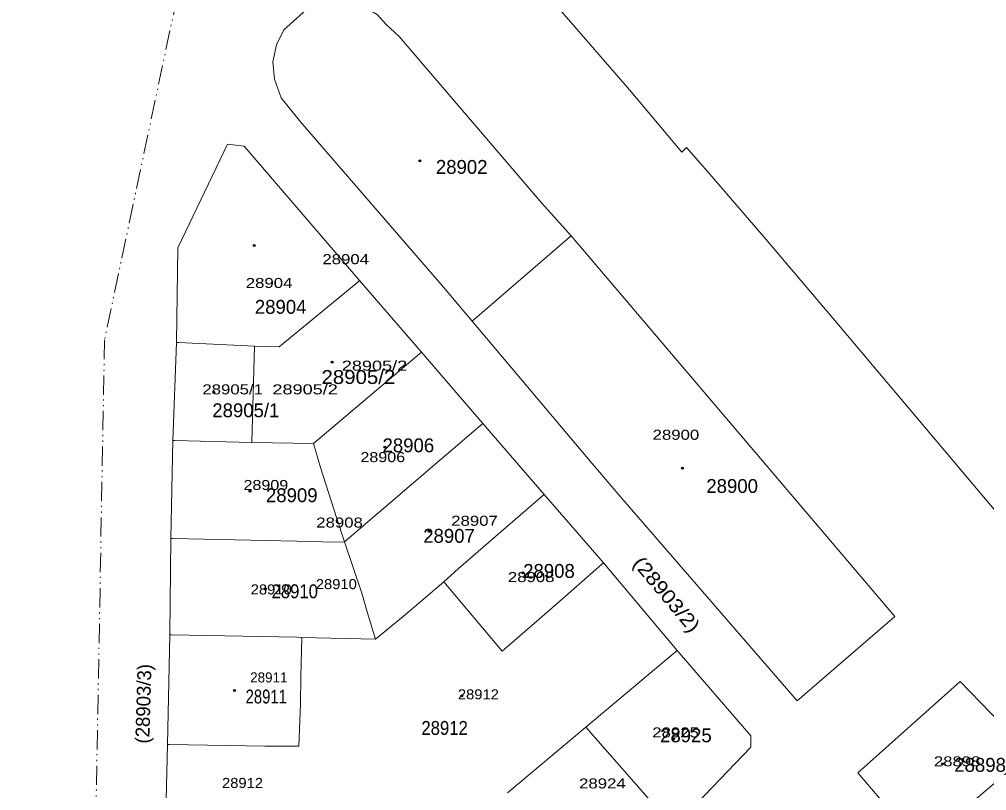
# Model space of a CAD drawing. Extents: x 650553 to 652508, y 239277 to 241647.
# Drawn here: x 650553 to 650803.9, y 240505.5 to 240705.5 of the extents above; entities that cross this region are included whole.
import ezdxf

# ---------------------------------------------------------------- set-up
doc = ezdxf.new("R2010")
doc.units = 0
doc.header["$PDMODE"] = 32
doc.header["$PDSIZE"] = 0.5
doc.linetypes.add('DASH_DOUBLE_DOT', pattern=[9.2, 5, -1.2, 0.3, -1.2, 0.3, -1.2])
for name, color, linetype in [('19', 7, 'Continuous'), ('20', 7, 'Continuous'), ('6', 7, 'Continuous')]:
    doc.layers.add(name, color=color, linetype=linetype)
for name, color, linetype, lineweight in [('3', 7, 'Continuous', 13), ('5', 7, 'Continuous', 13), ('52', 7, 'DASH_DOUBLE_DOT', 13)]:
    doc.layers.add(name, color=color, linetype=linetype, lineweight=lineweight)

msp = doc.modelspace()

# ---------------------------------------------------------------- linework, layer by layer
at = {"layer": '3'}
for points in [[(650806.33, 240577.79), (650765.444, 240626.293), (650746.606, 240648.49), (650731.529, 240665.947), (650726.049, 240672.268), (650724.783, 240671.099), (650711.274, 240687.205), (650684, 240718.73), (650670.237, 240734.531)], [(650696.1, 240649.407), (650688.549, 240657.818), (650651.503, 240701.065), (650648.168, 240704.201), (650645.87, 240706.648), (650641.372, 240709.429), (650637.2, 240710.453), (650632.875, 240710.256), (650628.245, 240708.762), (650621.636, 240702.791), (650619.734, 240698.95), (650618.767, 240694.523), (650619.141, 240689.967), (650620.905, 240685.179), (650625.93, 240678.961), (650663.001, 240636.096), (650670.4, 240627.253)], [(650641.253, 240637.783), (650611.303, 240672.672), (650607.004, 240673.162), (650594.146, 240646.254), (650593.75, 240621.72), (650592.8, 240596.31), (650592.32, 240570.89), (650591.99, 240545.96), (650591.4, 240517.48), (650590.91, 240496.01)], [(650780.09, 240550.71), (650734.888, 240603.764), (650696.1, 240649.407)], [(650722.72, 240495.97), (650742.7, 240516.78), (650742.7, 240519.73), (650723.62, 240541.87), (650704.48, 240564.63), (650689.1, 240582.35), (650673.18, 240600.74), (650657.314, 240619.179), (650641.253, 240637.783)], [(650670.4, 240627.253), (650701.485, 240590.479), (650709.011, 240581.661), (650754.7, 240528.83), (650780.09, 240550.71)], [(650779.1, 240500), (650770.45, 240510.11), (650796.97, 240533.86), (650812.73, 240517.56)]]:
    msp.add_lwpolyline(points, dxfattribs=at)
at = {"layer": '5'}
for points in [[(650670.4, 240627.253), (650695.6, 240648.976), (650696.1, 240649.407)], [(650614.03, 240620.81), (650620.4, 240620.61), (650640.753, 240637.371), (650641.253, 240637.783)], [(650593.75, 240621.72), (650594.25, 240621.698), (650614.03, 240620.81), (650613.32, 240595.83)], [(650629.27, 240595.52), (650656.814, 240618.757), (650657.314, 240619.179)], [(650637.36, 240570.04), (650672.68, 240600.311), (650673.18, 240600.74)], [(650592.8, 240596.31), (650593.3, 240596.298), (650613.32, 240595.83)], [(650637.36, 240570.04), (650635.24, 240576.37), (650631.13, 240589.31), (650629.27, 240595.52), (650613.32, 240595.83)], [(650677.15, 240572.05), (650688.6, 240581.919), (650689.1, 240582.35)], [(650592.32, 240570.89), (650592.82, 240570.879), (650625, 240570.19)], [(650663.13, 240559.71), (650666.82, 240563.02), (650677.15, 240572.05)], [(650645.39, 240544.78), (650643.24, 240551.93), (650641.82, 240556.75), (650637.36, 240570.04), (650634.94, 240569.98), (650625, 240570.19)], [(650693.18, 240554.67), (650703.98, 240564.189), (650704.48, 240564.63)], [(650626.27, 240545.26), (650645.39, 240544.78), (650652.57, 240550.69), (650663.13, 240559.71), (650678.2, 240541.67), (650690.5, 240552.34), (650693.18, 240554.67)], [(650625, 240545.29), (650592.49, 240545.95), (650591.99, 240545.96)], [(650625, 240517.02), (650625.52, 240517.02), (650625.88, 240528.01), (650626.04, 240535.13), (650626.27, 240545.26), (650625, 240545.29)], [(650699.96, 240521.98), (650723.12, 240541.45), (650723.62, 240541.87)], [(650679.64, 240504.99), (650699.96, 240521.98), (650719.19, 240500)], [(650591.4, 240517.48), (650591.9, 240517.472), (650616.67, 240517.1), (650625, 240517.02)], [(650797.15, 240500), (650814.38, 240514.674), (650814.88, 240515.1)]]:
    msp.add_lwpolyline(points, dxfattribs=at)
at = {"layer": '52'}
msp.add_lwpolyline([(650605.404, 240765.589), (650575.102, 240622.376), (650564.111, 240019.547), (650563.292, 239912.239), (650561.967, 239831.306), (650558.948, 239635.138), (650557.76, 239590.469), (650555.824, 239499.761), (650555.114, 239481.758), (650553.994, 239393.396), (650554.019, 239393.395), (650553.222, 239318.763), (650553.006, 239301.006), (650586.911, 239277.281)], dxfattribs=at)
at = {"layer": '6'}
for p in [(650656.884, 240668.853), (650613.943, 240646.886), (650634.115, 240616.651), (650603.477, 240608.775), (650647.785, 240594.609), (650725.006, 240589.118), (650612.82, 240583.145), (650659.254, 240572.76), (650683.601, 240562.01), (650616.802, 240557.835), (650608.824, 240531.49), (650667.764, 240530.085), (650722.669, 240518.92), (650792.456, 240512.485)]:
    msp.add_point(p, dxfattribs=at)

# ---------------------------------------------------------------- texts
at = {"layer": '19'}
for s, p in [('28902', (650661.031, 240665.447)), ('28904', (650614.083, 240629.168)), ('28905/1', (650603.047, 240602.351)), ('28906', (650647.196, 240593.254)), ('28900', (650731.172, 240582.718)), ('28909', (650616.964, 240580.325)), ('28907', (650657.753, 240569.79)), ('28908', (650683.665, 240560.691)), ('28925', (650719.176, 240518.071)), ('28898', (650795.476, 240510.41))]:
    msp.add_text(s, height=3.6, dxfattribs=at).set_placement(p)
for s, width, p in [('28905/2', 1.1, (650631.36, 240610.971)), ('28910', 0.9, (650618.403, 240555.424)), ('28911', 0.8, (650611.685, 240528.129)), ('28912', 0.9, (650657.273, 240519.988))]:
    msp.add_text(s, height=3.6, dxfattribs=dict(at, width=width)).set_placement(p)
at = {"layer": '19', "width": 1.15}
msp.add_text('(28903/2)', height=3.6, rotation=309.894, dxfattribs=at).set_placement((650711.888, 240564.357))
at = {"layer": '19'}
msp.add_text('(28903/3)', height=3.6, rotation=88.329, dxfattribs=at).set_placement((650586.678, 240517.704))
at = {"layer": '20'}
for s, width, p in [('28904', 1.25, (650631.599, 240642.034)), ('28904', 1.25, (650611.724, 240635.86)), ('28905/2', 1.35, (650636.63, 240614.423)), ('28905/1', 1.25, (650600.47, 240608.273)), ('28905/2', 1.35, (650618.638, 240608.273)), ('28900', 1.25, (650717.24, 240596.502)), ('28906', 1.2, (650641.458, 240590.71)), ('28909', 1.2, (650611.131, 240583.483)), ('28908', 1.25, (650630.005, 240573.742)), ('28907', 1.25, (650665.008, 240574.198)), ('28910', 1.1, (650629.895, 240557.781)), ('28908', 1.25, (650679.706, 240559.605)), ('28910', 1.1, (650613.003, 240556.402)), ('28912', 1.1, (650666.739, 240529.203)), ('28925', 1.25, (650717.156, 240519.323)), ('28898', 1.25, (650790.169, 240511.828)), ('28912', 1.1, (650605.564, 240506.229)), ('28924', 1.25, (650698.169, 240506.098))]:
    msp.add_text(s, height=2.6, dxfattribs=dict(at, width=width)).set_placement(p)
msp.add_text('28911', height=2.6, dxfattribs=at).set_placement((650612.87, 240533.587))

doc.saveas('drawing.dxf')
